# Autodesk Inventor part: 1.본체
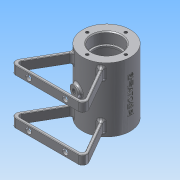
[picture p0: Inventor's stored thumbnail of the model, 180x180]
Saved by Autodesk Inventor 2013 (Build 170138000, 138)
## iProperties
Created: 2016-03
Part Number: 1.본체
Material: 알루미늄 6061
Document SubType Name: Modeling
Designer: Administrator
Mass: 211.191 g
Surface Area: 327.687 cm^2
Volume: 77.9302 cm^3
Density: 2.71 g/cm^3
Author: Administrator
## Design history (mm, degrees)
sketch "스케치1"
  geometry: C1 r 26 at (0, 0); 1 further point
  constraints: 1 centre point, 1 coincident
  dimensions: "d0" = 52 diameter of C1
extrude "돌출1" new body sketch "스케치1" stored distance "d1" = 70; taper "d2" = 0 deg
sketch "스케치2"
  geometry: C1 r 21 at (0, 0); 1 further point
  constraints: 1 centre point, 1 coincident
  dimensions: "d3" = 42 diameter of C1
extrude "돌출2" cut sketch "스케치2" stored distance "d4" = 42; taper "d5" = 0 deg
hole "구멍1" diameter "d8" = 28; stored, may be unused: countersink angle "d12" = 90 deg, drill point angle "d14" = 0 deg; dims "d6" = 10, "d7" = 10, "d9" = 6, "d10" = 32, "d11" = 12, "d13" = 8
hole "구멍2" diameter "d17" = 28; stored, may be unused: countersink angle "d21" = 90 deg, drill point angle "d23" = 0 deg; dims "d15" = 10, "d16" = 10, "d18" = 6, "d19" = 32, "d20" = 12, "d22" = 8
sketch "스케치3"
  geometry: 1 further point
sketch "스케치4" dims "d24" = 42
  geometry: C1 r 26 at (0, 0) reference; 3 further points
  constraints: 2 vertical alignment, 1 coincident, 2 other
hole "구멍3" sketch "스케치4" at (0, 21) diameter "d25" = 3.242; stored, may be unused: countersink angle "d29" = 90 deg, drill point angle "d31" = 118 deg; dims "d26" = 8, "d27" = 32, "d28" = 12, "d30" = 10
sketch "스케치5"
  geometry: 1 further point
node "작업 평면3"
sketch "스케치7"
  geometry: C1 r 5 at (0, 0); 1 further point
  constraints: 1 centre point, 1 coincident
  dimensions: "d37" = 10 diameter of C1
extrude "돌출3" join sketch "스케치7" stored distance "d38" = 42; taper "d39" = 0 deg
sketch "스케치8"
  geometry: C1 r 1.621 at (21, 0) reference; C2 r 1.621 at (0, -21) reference; C3 r 1.621 at (-21, 0) reference; C4 r 1.621 at (0, 21) reference; C5 r 16 at (0, 0) reference; C6 r 26 at (0, 0) reference
node "작업 평면4"
sketch "스케치10"
  geometry: L1 (-14.183, -21.791)-(-37.398, -62); L2 (-37.398, -62)-(37.398, -62); L3 (37.398, -62)-(14.183, -21.791); L4 (16.613, -20)-(42.594, -65); L5 (42.594, -65)-(-42.594, -65); L6 (-42.594, -65)-(-16.613, -20); L7 (0, 0)-(0, -60.192); C1 r 21 at (0, 0) reference; A1 r 26 centre (0, 0) between (-14.183, -21.791) and (14.183, -21.791) reference; 1 further point
  constraints: 14 end point, 4 point on circle, 2 equal length, 2 parallel, 1 horizontal, 1 perpendicular
  dimensions: "d41" = 30 deg angle of L7 L3; "d42" = 30 deg angle of L1 L7; "d43" = 30 deg angle of L7 L6; "d44" = 3 distance between parallel lines of L3 L4; "d46" = 65 distance from line of L5 point (0, 0); "d47" = 3 distance between parallel lines of L2 L5; "d142" = 45 distance from line of L5 L4.start
extrude "돌출4" join sketch "스케치10" distance "d48" = 10; taper "d49" = 0 deg
fillet "모깎기1" dims "d53" = 5, "d54" = 3
hole "구멍4" diameter "d57" = 4.917; stored, may be unused: countersink angle "d61" = 90 deg, drill point angle "d63" = 118 deg; dims "d55" = 10, "d56" = 10, "d58" = 8, "d59" = 32, "d60" = 12, "d62" = 17.75
sketch "스케치13"
  geometry: L1 (0, 0)-(67.868, 0) reference; L2 (0, 10)-(67.868, 10) reference; L3 (33.934, 10)-(33.934, 0); C1 r 3 at (13.934, 5); C2 r 3 at (53.934, 5); 1 further point
  constraints: 2 centre point, 2 end point, 2 midpoint
  dimensions: "d83" = 6 diameter of C1; "d84" = 6 diameter of C2; "d85" = 5 distance from line of L2 C2.centre; "d86" = 40 distance of C1.centre C2.centre; "d87" = 20 distance from line of C1.centre L3
extrude "돌출7" cut sketch "스케치13" stored distance "d88" = 12; taper "d89" = 0 deg
fillet "모깎기2" dims "d90" = 0.5
chamfer "모따기1" distance "d91" = 1; stored, may be unused: second distance "d92" = 2, angle "d93" = 45 deg
fillet "모깎기3" dims "d94" = 0.3
fillet "모깎기4" dims "d95" = 2
fillet "모깎기5" dims "d96" = 3
node "작업 평면5"
sketch "스케치14"
  geometry: L1 (-46.021, -20)-(-42.021, -20) reference; L2 (-41.021, -20.5)-(-41.021, -29.5) reference; L3 (-42.021, -30)-(-46.021, -30) reference; L4 (-41.021, 29.5)-(-41.021, 20.5) reference; L5 (-42.021, 20)-(-46.021, 20) reference; L6 (-46.021, 30)-(-42.021, 30) reference; L7 (26, -35)-(26, 35) reference; L8 (26, -35)-(26, 35) reference; L9 (-47.021, -29.5)-(-47.021, -20.5) reference; L10 (-64.5, -20)-(-62.5, -20) reference; L11 (-62, -20.5)-(-62, -29.5) reference; L12 (-62.5, -30)-(-64.5, -30) reference; L13 (-65, -29.5)-(-65, -20.5) reference; L14 (-64.5, 30)-(-62.5, 30) reference; L15 (-62, 29.5)-(-62, 20.5) reference; L16 (-62.5, 20)-(-64.5, 20) reference; L17 (-65, 20.5)-(-65, 29.5) reference; L18 (-47.021, 20.5)-(-47.021, 29.5) reference; A1 r 0.5 centre (-64.5, -20.5) between (-64.5, -20) and (-65, -20.5) reference; A2 r 0.5 centre (-62.5, -20.5) between (-62, -20.5) and (-62.5, -20) reference; A3 r 0.5 centre (-62.5, -29.5) between (-62.5, -30) and (-62, -29.5) reference; A4 r 0.5 centre (-64.5, -29.5) between (-65, -29.5) and (-64.5, -30) reference; A5 r 0.5 centre (-64.5, 29.5) between (-64.5, 30) and (-65, 29.5) reference; A6 r 0.5 centre (-62.5, 29.5) between (-62, 29.5) and (-62.5, 30) reference; A7 r 0.5 centre (-62.5, 20.5) between (-62.5, 20) and (-62, 20.5) reference; A8 r 0.5 centre (-64.5, 20.5) between (-65, 20.5) and (-64.5, 20) reference; 10 further points; 8 other entities
  constraints: 9 other
  dimensions: "d98" = 0 horizontal distance of point (0, 0) point (0, -0.112); "d99" = 26 distance from line of L7 point (0, -0.112) (derived)
feature "엠보싱1" sketch "스케치14" dims "d100" = 0.5, "d101" = 0
fillet "모깎기6" dims "d105" = 3
sketch "스케치15"
  geometry: 1 further point
sketch "스케치16"
  geometry: L1 (0, 0)-(0, -49.773); L2 (25.89, 2.385)-(26.392, 2.385) reference; L3 (26.371, -2.615)-(25.868, -2.615) reference; L4 (2.458, 20.856)-(2.458, 29) reference; L5 (2.458, 29)-(5, 29) reference; L6 (5, 29)-(5, 27.111) reference; L7 (-5, 27.111)-(-5, 29) reference; L8 (-5, 29)-(-2.458, 29) reference; L9 (-2.458, 29)-(-2.458, 20.856) reference; L10 (-15.167, -21.118)-(-16.377, -25.635); L11 (-16.377, -25.635)-(-4.786, -28.741); L12 (-4.786, -28.741)-(-3.97, -25.695); A1 r 26.5 centre (0, 0) between (26.371, -2.615) and (26.392, 2.385) reference; A2 r 21 centre (0, 0) between (-2.458, 20.856) and (2.458, 20.856) reference; A3 r 26 centre (0, 0) between (25.89, 2.385) and (6.5, 25.174) reference; A4 r 26 centre (0, 0) between (-6.5, 25.174) and (25.868, -2.615) reference
  constraints: 8 end point, 1 parallel, 1 perpendicular, 1 vertical, 2 other
  node "절단 모서리 투영6"
sketch "스케치19"
  geometry: 1 further point
sketch "스케치20"
  geometry: L1 (0, 0)-(0, -41.75); L2 (0, 0)-(-11.03, -41.165); L3 (-7.506, -28.012)-(-1.71, -29.565); L4 (25.89, 2.385)-(26.392, 2.385) reference; L5 (26.371, -2.615)-(25.868, -2.615) reference; L6 (-5, 27.111)-(-5, 29) reference; L7 (-5, 29)-(-2.458, 29) reference; L8 (-2.458, 29)-(-2.458, 20.856) reference; L9 (2.458, 20.856)-(2.458, 29) reference; L10 (2.458, 29)-(5, 29) reference; L11 (5, 29)-(5, 27.111) reference; L12 (-1.71, -29.565)-(-0.752, -25.989); L13 (-7.506, -28.012)-(-13.301, -26.459); L14 (-13.301, -26.459)-(-12.343, -22.883); A1 r 26.5 centre (0, 0) between (26.371, -2.615) and (26.392, 2.385) reference; A2 r 26 centre (0, 0) between (-6.5, 25.174) and (25.868, -2.615) reference; A3 r 21 centre (0, 0) between (-2.458, 20.856) and (2.458, 20.856) reference; A4 r 26 centre (0, 0) between (25.89, 2.385) and (6.5, 25.174) reference
  constraints: 12 end point, 4 perpendicular, 2 point on circle, 1 point on line, 1 vertical, 2 other
  dimensions: "d122" = 15 deg angle of L1 L2; "d123" = 6 distance between parallel lines of L12 L2; "d125" = 29 distance from line of L13 L1.start; "d126" = 6 distance between parallel lines of L14 L2
extrude "돌출10" join sketch "스케치20" stored distance "d127" = 12; taper "d128" = 0 deg
sketch "스케치21"
  geometry: L1 (0, 0)-(0, 12) reference; L2 (-12, 12)-(0, 12) reference; L3 (-12, 0)-(-12, 12) reference; L4 (0, 0)-(-12, 0) reference; C1 r 6 at (-6, 6); 1 further point
  constraints: 1 centre point, 1 coincident
  dimensions: "d129" = 12 diameter of C1
extrude "돌출11" cut sketch "스케치21" stored distance "d130" = 12; taper "d131" = 0 deg
hole "구멍6" diameter "d134" = 4.917; stored, may be unused: countersink angle "d138" = 90 deg, drill point angle "d140" = 0 deg; dims "d132" = 10, "d133" = 10, "d135" = 8, "d136" = 32, "d137" = 12, "d139" = 17.75
fillet "모깎기7" dims "d141" = 2
sketch "스케치22" dims "d143" = 42
  geometry: C1 r 17 at (0, 0) reference; 2 further points
  constraints: 1 coincident, 1 vertical alignment, 2 other
hole "구멍7" sketch "스케치22" at (0, 21) diameter "d144" = 3.242; stored, may be unused: countersink angle "d148" = 90 deg, drill point angle "d150" = 118 deg; dims "d145" = 8, "d146" = 32, "d147" = 12, "d149" = 10
sketch "스케치17"
  geometry: L1 (25.89, 2.385)-(26.392, 2.385) reference; L2 (26.371, -2.615)-(25.868, -2.615) reference; L3 (13.836, -23.656)-(14.501, -26.138) reference; L4 (14.501, -26.138)-(11.08, -27.054) reference; L5 (11.08, -27.054)-(8.924, -19.009) reference; L6 (2.458, 20.856)-(2.458, 29) reference; L7 (2.458, 29)-(5, 29) reference; L8 (5, 29)-(5, 27.111) reference; L9 (-5, 27.111)-(-5, 29) reference; L10 (-5, 29)-(-2.458, 29) reference; L11 (-2.458, 29)-(-2.458, 20.856) reference; L12 (4.251, -20.565)-(6.331, -28.327) reference; L13 (6.331, -28.327)-(2.91, -29.243) reference; L14 (2.91, -29.243)-(2.437, -27.478) reference; L15 (0, 0)-(0, -44.249); L16 (-7.597, -28.353)-(0, 0); L17 (-7.597, -28.353)-(-1.802, -29.906); L18 (-7.597, -28.353)-(-13.393, -26.8); L19 (-13.393, -26.8)-(-12.343, -22.883); L20 (-1.802, -29.906)-(-0.752, -25.989); A1 r 26.5 centre (0, 0) between (26.371, -2.615) and (26.392, 2.385) reference; A2 r 26 centre (0, 0) between (14.641, -21.486) and (25.868, -2.615) reference; A3 r 21 centre (0, 0) between (8.924, -19.009) and (2.458, 20.856) reference; A4 r 26 centre (0, 0) between (25.89, 2.385) and (6.5, 25.174) reference; A5 r 26 centre (0, 0) between (-6.5, 25.174) and (0.469, -25.996) reference; A6 r 21 centre (0, 0) between (-2.458, 20.856) and (4.251, -20.565) reference; 1 further point
  constraints: 12 end point, 2 parallel, 2 perpendicular, 2 point on circle, 1 collinear, 4 other
  dimensions: "d111" = 29.35309 distance of L16.start L15.start; "d112" = 15 deg angle of L16 L15; "d115" = 6 distance of L16.start L18.end; "d116" = 6 distance of L16.start L17.end
extrude "돌출8" join sketch "스케치17" stored distance "d117" = 12; taper "d118" = 0 deg
sketch "스케치18"
  geometry: L1 (0, 0)-(0, 12) reference; L2 (-12, 12)-(0, 12) reference; L3 (-12, 0)-(-12, 12) reference; L4 (0, 0)-(-12, 0) reference; C1 r 6 at (-6, 6); 1 further point
  constraints: 1 centre point, 1 coincident
  dimensions: "d119" = 12 diameter of C1
extrude "돌출9" cut sketch "스케치18" stored distance "d120" = 12; taper "d121" = 0 deg
node "솔리드1"
pattern_circular "원형 패턴1" dims angle "d33" = 360 deg
pattern_circular "원형 패턴2" dims angle "d51" = 360 deg
pattern_linear "직사각형 패턴1" dims "d104" = 50
pattern_circular "원형 패턴3" dims angle "d152" = 360 deg
node "절단 모서리 투영3"
node "절단 모서리 투영5"
node "절단 모서리 투영7"
node "절단 모서리 투영8"
other parameters: "d36" = 29, "d97" = 28.75
